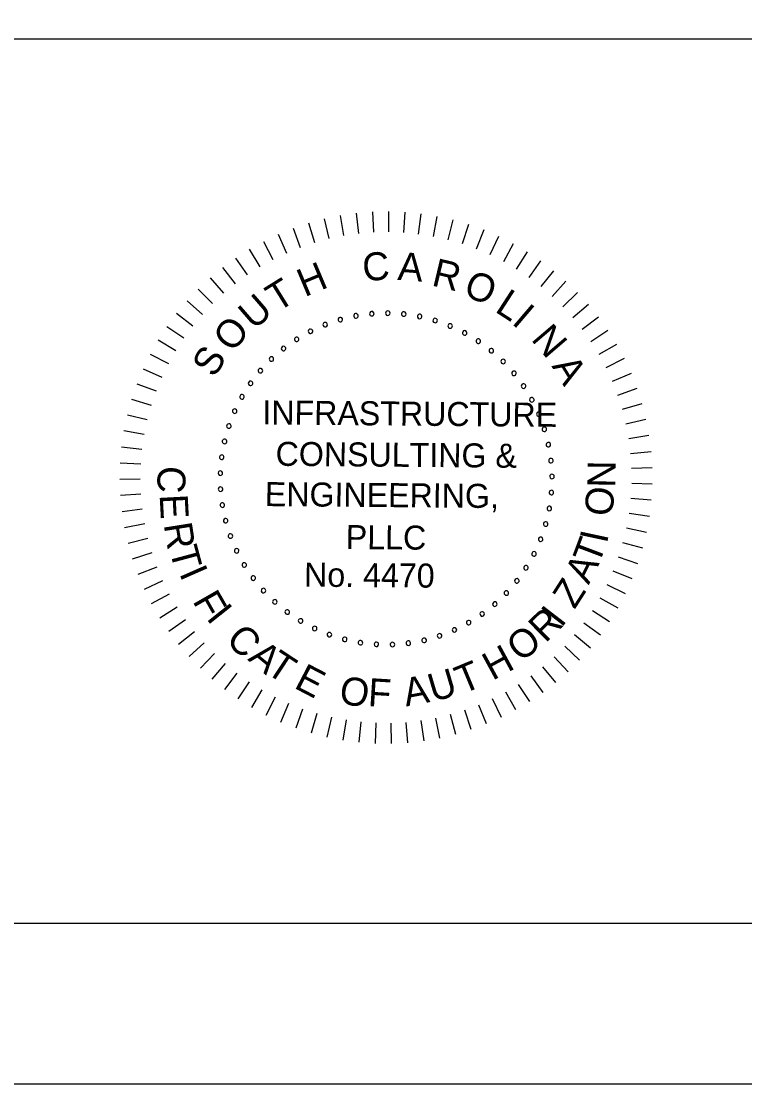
# Model space of a CAD drawing. Extents: x -149.6 to -53.3, y -21.7 to 37.
# Drawn here: x -82.41 to -76.41, y -21.66 to -12.85 of the extents above; entities that cross this region are included whole.
import ezdxf

# ---------------------------------------------------------------- set-up
doc = ezdxf.new("R2010")
doc.units = 0
for name, color, linetype in [('BR_BORDER LINES', 7, 'Continuous'), ('BR_TEXT', 7, 'Continuous'), ('Level 31', 7, 'Continuous')]:
    doc.layers.add(name, color=color, linetype=linetype)

msp = doc.modelspace()

# ---------------------------------------------------------------- linework, layer by layer
at = {"layer": 'BR_BORDER LINES'}
for p, q in [((-89.2486, -12.993), (-74.9414, -12.993)), ((-144.7168, -20.3267), (-54.9406, -20.3267))]:
    msp.add_line(p, q, dxfattribs=at)
at = {"layer": 'BR_TEXT'}
for p, q in [((-79.6331, -14.438), (-79.6138, -14.6067)), ((-79.4989, -14.427), (-79.4899, -14.5965)), ((-79.3643, -14.4242), (-79.3657, -14.5939)), ((-79.2298, -14.4295), (-79.2415, -14.5989)), ((-79.0958, -14.4431), (-79.1179, -14.6115)), ((-80.0281, -14.5198), (-79.9784, -14.6821)), ((-79.8981, -14.4845), (-79.8585, -14.6496)), ((-79.7663, -14.4572), (-79.7368, -14.6244)), ((-78.963, -14.4648), (-78.9952, -14.6315)), ((-78.8317, -14.4946), (-78.8741, -14.659)), ((-78.7025, -14.5323), (-78.7548, -14.6938)), ((-80.2803, -14.6137), (-80.2112, -14.7688)), ((-80.1556, -14.5629), (-80.0961, -14.7219)), ((-78.5758, -14.5779), (-78.6378, -14.7359)), ((-80.4016, -14.672), (-80.3232, -14.8226)), ((-78.4521, -14.631), (-78.5237, -14.785)), ((-78.3319, -14.6916), (-78.4127, -14.8409)), ((-80.5191, -14.7376), (-80.4317, -14.8832)), ((-78.2156, -14.7594), (-78.3054, -14.9035)), ((-80.7412, -14.8897), (-80.6367, -15.0235)), ((-80.6325, -14.8103), (-80.5364, -14.9502)), ((-78.1036, -14.8342), (-78.2021, -14.9726)), ((-80.8448, -14.9756), (-80.7324, -15.1028)), ((-77.9965, -14.9157), (-78.1031, -15.0478)), ((-80.9431, -15.0677), (-80.8231, -15.1878)), ((-77.8945, -15.0036), (-78.009, -15.1289)), ((-77.798, -15.0975), (-77.92, -15.2156)), ((-81.0355, -15.1655), (-80.9084, -15.2781)), ((-77.7075, -15.1971), (-77.8364, -15.3076)), ((-81.1218, -15.2689), (-80.9881, -15.3735)), ((-77.6231, -15.302), (-77.7586, -15.4045)), ((-81.2016, -15.3773), (-81.0618, -15.4736)), ((-77.5454, -15.4119), (-77.6868, -15.5059)), ((-81.2747, -15.4903), (-81.1292, -15.5779)), ((-77.4745, -15.5264), (-77.6213, -15.6115)), ((-81.3407, -15.6077), (-81.1902, -15.6862)), ((-77.4107, -15.6449), (-77.5625, -15.721)), ((-81.3995, -15.7288), (-81.2444, -15.798)), ((-77.3542, -15.7671), (-77.5103, -15.8338)), ((-81.4508, -15.8532), (-81.2918, -15.9129)), ((-77.3053, -15.8925), (-77.4652, -15.9496)), ((-81.4943, -15.9806), (-81.332, -16.0305)), ((-77.2641, -16.0207), (-77.4272, -16.0679)), ((-81.5301, -16.1104), (-81.365, -16.1503)), ((-77.2308, -16.1512), (-77.3965, -16.1883)), ((-81.5579, -16.2421), (-81.3907, -16.2719)), ((-77.2056, -16.2834), (-77.3732, -16.3104)), ((-81.5775, -16.3753), (-81.4089, -16.3948)), ((-77.1884, -16.4169), (-77.3574, -16.4336)), ((-81.5891, -16.5094), (-81.4195, -16.5186)), ((-77.1794, -16.5512), (-77.3491, -16.5576)), ((-81.5924, -16.644), (-81.4226, -16.6428)), ((-77.1787, -16.6859), (-77.3484, -16.6819)), ((-81.5875, -16.7786), (-81.4181, -16.767)), ((-77.1861, -16.8203), (-77.3553, -16.806)), ((-81.5744, -16.9125), (-81.4061, -16.8907)), ((-77.2017, -16.954), (-77.3697, -16.9294)), ((-81.5532, -17.0455), (-81.3865, -17.0134)), ((-77.2254, -17.0865), (-77.3916, -17.0517)), ((-81.5239, -17.1769), (-81.3595, -17.1347)), ((-77.2572, -17.2173), (-77.421, -17.1725)), ((-81.4867, -17.3063), (-81.3251, -17.2541)), ((-77.2969, -17.346), (-77.4576, -17.2912)), ((-81.4416, -17.4331), (-81.2835, -17.3712)), ((-77.3444, -17.472), (-77.5014, -17.4075)), ((-81.3889, -17.557), (-81.2349, -17.4856)), ((-77.3994, -17.5948), (-77.5522, -17.5209)), ((-81.3288, -17.6774), (-81.1794, -17.5968)), ((-81.2614, -17.794), (-81.1172, -17.7044)), ((-77.4618, -17.7141), (-77.6099, -17.631)), ((-77.5314, -17.8293), (-77.6741, -17.7373)), ((-81.187, -17.9062), (-81.0485, -17.8079)), ((-77.6079, -17.9401), (-77.7447, -17.8396)), ((-81.1059, -18.0137), (-80.9737, -17.9072)), ((-77.691, -18.046), (-77.8215, -17.9374)), ((-81.0185, -18.116), (-80.893, -18.0016)), ((-77.7804, -18.1467), (-77.904, -18.0303)), ((-80.9249, -18.2128), (-80.8066, -18.091)), ((-77.8758, -18.2417), (-77.992, -18.118)), ((-80.8256, -18.3037), (-80.715, -18.1749)), ((-77.9768, -18.3307), (-78.0853, -18.2001)), ((-80.721, -18.3884), (-80.6184, -18.2531)), ((-80.6114, -18.4666), (-80.5172, -18.3253)), ((-78.083, -18.4134), (-78.1833, -18.2765)), ((-80.4972, -18.5379), (-80.4119, -18.3912)), ((-78.3096, -18.5587), (-78.3925, -18.4105)), ((-78.1941, -18.4895), (-78.2859, -18.3467)), ((-80.3789, -18.6022), (-80.3027, -18.4505)), ((-80.2569, -18.6591), (-80.19, -18.503)), ((-78.4291, -18.6207), (-78.5028, -18.4677)), ((-80.1317, -18.7085), (-80.0744, -18.5486)), ((-80.0036, -18.7501), (-79.9563, -18.5871)), ((-78.6783, -18.7222), (-78.7328, -18.5615)), ((-78.5521, -18.6752), (-78.6164, -18.5181)), ((-79.8733, -18.7839), (-79.836, -18.6182)), ((-79.7412, -18.8096), (-79.714, -18.642)), ((-79.6077, -18.8273), (-79.5908, -18.6583)), ((-79.4734, -18.8367), (-79.4669, -18.6671)), ((-79.3388, -18.838), (-79.3426, -18.6683)), ((-79.2044, -18.8311), (-79.2185, -18.6619)), ((-79.0706, -18.816), (-79.095, -18.6479)), ((-78.938, -18.7927), (-78.9726, -18.6265)), ((-78.8071, -18.7614), (-78.8517, -18.5976))]:
    msp.add_line(p, q, dxfattribs=at)
for centre, start, end in [((-79.7646, -15.3206), 16.14222, 196.14222), ((-79.7646, -15.3206), 196.14222, 16.14222), ((-79.6352, -15.2902), 10.60376, 190.60376), ((-79.6352, -15.2902), 190.60376, 10.60376), ((-79.5036, -15.2723), 5.06529, 185.06529), ((-79.5036, -15.2723), 185.06529, 5.06529), ((-79.3708, -15.2672), 359.52683, 179.52683), ((-79.3708, -15.2672), 179.52683, 359.52683), ((-79.2381, -15.275), 173.98837, 353.98837), ((-79.2381, -15.275), 353.98837, 173.98837), ((-79.1068, -15.2956), 168.44991, 348.44991), ((-79.1068, -15.2956), 348.44991, 168.44991), ((-78.9781, -15.3287), 162.91145, 342.91145), ((-78.9781, -15.3287), 342.91145, 162.91145), ((-80.0114, -15.4182), 27.21914, 207.21914), ((-80.0114, -15.4182), 207.21914, 27.21914), ((-79.8904, -15.3634), 21.68068, 201.68068), ((-79.8904, -15.3634), 201.68068, 21.68068), ((-78.8533, -15.3741), 157.37299, 337.37299), ((-78.8533, -15.3741), 337.37299, 157.37299), ((-78.7333, -15.4313), 151.83453, 331.83453), ((-78.7333, -15.4313), 331.83453, 151.83453), ((-80.1267, -15.4844), 32.7576, 212.7576), ((-80.1267, -15.4844), 212.7576, 32.7576), ((-78.6195, -15.4998), 146.29606, 326.29606), ((-78.6195, -15.4998), 326.29606, 146.29606), ((-80.235, -15.5614), 38.29606, 218.29606), ((-80.235, -15.5614), 218.29606, 38.29606), ((-78.5128, -15.579), 140.7576, 320.7576), ((-78.5128, -15.579), 320.7576, 140.7576), ((-80.3353, -15.6485), 43.83453, 223.83453), ((-80.3353, -15.6485), 223.83453, 43.83453), ((-78.4142, -15.6682), 135.21914, 315.21914), ((-78.4142, -15.6682), 315.21914, 135.21914), ((-80.4268, -15.7449), 49.37299, 229.37299), ((-80.4268, -15.7449), 229.37299, 49.37299), ((-78.3247, -15.7664), 129.68068, 309.68068), ((-78.3247, -15.7664), 309.68068, 129.68068), ((-80.5086, -15.8496), 54.91145, 234.91145), ((-80.5086, -15.8496), 234.91145, 54.91145), ((-78.2451, -15.8728), 124.14222, 304.14222), ((-78.2451, -15.8728), 304.14222, 124.14222), ((-80.5798, -15.9618), 60.44991, 240.44991), ((-80.5798, -15.9618), 240.44991, 60.44991), ((-78.1762, -15.9864), 118.60376, 298.60376), ((-78.1762, -15.9864), 298.60376, 118.60376), ((-80.6399, -16.0803), 65.98837, 245.98837), ((-80.6399, -16.0803), 245.98837, 65.98837), ((-78.1185, -16.1061), 113.06529, 293.06529), ((-78.1185, -16.1061), 293.06529, 113.06529), ((-80.6883, -16.204), 71.52683, 251.52683), ((-80.6883, -16.204), 251.52683, 71.52683), ((-78.0727, -16.2308), 107.52683, 287.52683), ((-78.0727, -16.2308), 287.52683, 107.52683), ((-80.7246, -16.3319), 77.06529, 257.06529), ((-80.7246, -16.3319), 257.06529, 77.06529), ((-78.0391, -16.3594), 101.98837, 281.98837), ((-78.0391, -16.3594), 281.98837, 101.98837), ((-80.7483, -16.4626), 82.60376, 262.60376), ((-80.7483, -16.4626), 262.60376, 82.60376), ((-78.018, -16.4906), 96.44991, 276.44991), ((-78.018, -16.4906), 276.44991, 96.44991), ((-80.7592, -16.5951), 88.14222, 268.14222), ((-80.7592, -16.5951), 268.14222, 88.14222), ((-78.0098, -16.6232), 90.91145, 270.91145), ((-78.0098, -16.6232), 270.91145, 90.91145), ((-80.7574, -16.7279), 93.68068, 273.68068), ((-80.7574, -16.7279), 273.68068, 93.68068), ((-78.0144, -16.756), 85.37299, 265.37299), ((-78.0144, -16.756), 265.37299, 85.37299), ((-80.7427, -16.86), 99.21914, 279.21914), ((-80.7427, -16.86), 279.21914, 99.21914), ((-78.0317, -16.8878), 79.83453, 259.83453), ((-78.0317, -16.8878), 259.83453, 79.83453), ((-80.7154, -16.99), 104.7576, 284.7576), ((-80.7154, -16.99), 284.7576, 104.7576), ((-78.0617, -17.0172), 74.29606, 254.29606), ((-78.0617, -17.0172), 254.29606, 74.29606), ((-80.6756, -17.1168), 110.29606, 290.29606), ((-80.6756, -17.1168), 290.29606, 110.29606), ((-78.1041, -17.1432), 68.7576, 248.7576), ((-78.1041, -17.1432), 248.7576, 68.7576), ((-80.6238, -17.2392), 115.83453, 295.83453), ((-80.6238, -17.2392), 295.83453, 115.83453), ((-78.1584, -17.2645), 63.21914, 243.21914), ((-78.1584, -17.2645), 243.21914, 63.21914), ((-80.5604, -17.356), 121.37299, 301.37299), ((-80.5604, -17.356), 301.37299, 121.37299), ((-78.2242, -17.3799), 57.68068, 237.68068), ((-80.4861, -17.4661), 306.91145, 126.91145), ((-78.2242, -17.3799), 237.68068, 57.68068), ((-80.4861, -17.4661), 126.91145, 306.91145), ((-78.3008, -17.4885), 52.14222, 232.14222), ((-78.3008, -17.4885), 232.14222, 52.14222), ((-80.4014, -17.5686), 132.44991, 312.44991), ((-80.4014, -17.5686), 312.44991, 132.44991), ((-78.3875, -17.5892), 46.60376, 226.60376), ((-78.3875, -17.5892), 226.60376, 46.60376), ((-80.3073, -17.6623), 137.98837, 317.98837), ((-80.3073, -17.6623), 317.98837, 137.98837), ((-78.4835, -17.681), 41.06529, 221.06529), ((-78.4835, -17.681), 221.06529, 41.06529), ((-80.2045, -17.7466), 143.52683, 323.52683), ((-80.2045, -17.7466), 323.52683, 143.52683), ((-80.0941, -17.8206), 329.06529, 149.06529), ((-78.588, -17.7632), 35.52683, 215.52683), ((-78.588, -17.7632), 215.52683, 35.52683), ((-80.0941, -17.8206), 149.06529, 329.06529), ((-79.9771, -17.8835), 154.60376, 334.60376), ((-79.9771, -17.8835), 334.60376, 154.60376), ((-78.8181, -17.8954), 24.44991, 204.44991), ((-78.8181, -17.8954), 204.44991, 24.44991), ((-78.6999, -17.8348), 29.98837, 209.98837), ((-78.6999, -17.8348), 209.98837, 29.98837), ((-79.8546, -17.9349), 160.14222, 340.14222), ((-79.8546, -17.9349), 340.14222, 160.14222), ((-79.7276, -17.9742), 165.68068, 345.68068), ((-79.7276, -17.9742), 345.68068, 165.68068), ((-79.0694, -17.9809), 13.37299, 193.37299), ((-79.0694, -17.9809), 193.37299, 13.37299), ((-78.9417, -17.9442), 18.91145, 198.91145), ((-78.9417, -17.9442), 198.91145, 18.91145), ((-79.5975, -18.001), 171.21914, 351.21914), ((-79.5975, -18.001), 351.21914, 171.21914), ((-79.4654, -18.0152), 176.7576, 356.7576), ((-79.4654, -18.0152), 356.7576, 176.7576), ((-79.3325, -18.0166), 2.29606, 182.29606), ((-79.3325, -18.0166), 182.29606, 2.29606), ((-79.2001, -18.0051), 7.83453, 187.83453), ((-79.2001, -18.0051), 187.83453, 7.83453)]:
    msp.add_arc(centre, 0.0187, start, end, dxfattribs=at)
at = {"layer": 'Level 31'}
msp.add_lwpolyline([(-149.6056, -21.6598), (-53.6056, -21.6598), (-53.6056, 37.0068), (-149.6056, 37.0068)], close=True, dxfattribs=at)

# ---------------------------------------------------------------- texts
at = {"layer": 'BR_TEXT'}
for s, height, rotation, p in [('C', 0.2325, 4.72812, (-79.5721, -15.0044)), ('A', 0.2325, 355.69809, (-79.2936, -14.9912)), ('H', 0.2325, 22.78817, (-80.0597, -15.1362)), ('R', 0.2325, 346.66807, (-79.0155, -15.0365)), ('T', 0.2325, 31.81819, (-80.2859, -15.2632)), ('O', 0.2325, 337.63804, (-78.7548, -15.116)), ('L', 0.2325, 327.10802, (-78.4912, -15.2505)), ('U', 0.2325, 40.84822, (-80.4814, -15.4129)), ('I', 0.2325, 319.578, (-78.3511, -15.3514)), ('O', 0.2325, 49.87824, (-80.66, -15.6022)), ('N', 0.2325, 310.54797, (-78.1889, -15.4868)), ('S', 0.2325, 58.90827, (-80.8079, -15.8107)), ('A', 0.2325, 301.51795, (-78.0154, -15.7066)), ('INFRASTRUCTURE', 0.19939, 359.52683, (-80.4115, -16.1908)), ('CONSULTING &', 0.19939, 359.52683, (-80.3014, -16.5338)), ('C', 0.2325, 267.02504, (-81.2745, -16.5305)), ('N', 0.2325, 89.20849, (-77.484, -16.7165)), ('ENGINEERING,', 0.19939, 359.52683, (-80.3909, -16.8682)), ('O', 0.2325, 83.20849, (-77.5135, -16.9604)), ('E', 0.2325, 273.02504, (-81.2627, -16.7747)), ('R', 0.2325, 279.02504, (-81.2287, -17.0208)), ('PLLC', 0.19939, 359.52683, (-79.7198, -17.2244)), ('I', 0.2325, 77.90926, (-77.5549, -17.1852)), ('T', 0.2325, 285.02504, (-81.1823, -17.2309)), ('T', 0.2325, 69.39539, (-77.6234, -17.3652)), ('I', 0.2325, 293.77127, (-81.1031, -17.4258)), ('No. 4470', 0.19939, 359.52683, (-80.0652, -17.5361)), ('A', 0.2325, 63.39539, (-77.7055, -17.5261)), ('Z', 0.2325, 57.39539, (-77.8224, -17.7297)), ('F', 0.2325, 299.77127, (-80.9933, -17.6553)), ('I', 0.2325, 308.52683, (-80.881, -17.7989)), ('I', 0.2325, 52.33388, (-77.9319, -17.8835)), ('R', 0.2325, 44.52683, (-78.0636, -18.0096)), ('C', 0.2325, 314.52683, (-80.7227, -17.9859)), ('O', 0.2325, 38.52683, (-78.2678, -18.1695)), ('A', 0.2325, 320.52683, (-80.5383, -18.1421)), ('T', 0.2325, 326.52683, (-80.3931, -18.2447)), ('H', 0.2325, 28.52683, (-78.5028, -18.3188)), ('T', 0.2325, 22.52683, (-78.7513, -18.4302)), ('E', 0.2325, 332.52683, (-80.1569, -18.3722)), ('U', 0.2325, 16.52683, (-78.9959, -18.4952)), ('O', 0.2325, 350.52683, (-79.7832, -18.5025)), ('F', 0.2325, 356.52683, (-79.5393, -18.5268)), ('A', 0.2325, 10.52683, (-79.2196, -18.5312))]:
    msp.add_text(s, height=height, rotation=rotation, dxfattribs=at).set_placement(p)

doc.saveas('drawing.dxf')
